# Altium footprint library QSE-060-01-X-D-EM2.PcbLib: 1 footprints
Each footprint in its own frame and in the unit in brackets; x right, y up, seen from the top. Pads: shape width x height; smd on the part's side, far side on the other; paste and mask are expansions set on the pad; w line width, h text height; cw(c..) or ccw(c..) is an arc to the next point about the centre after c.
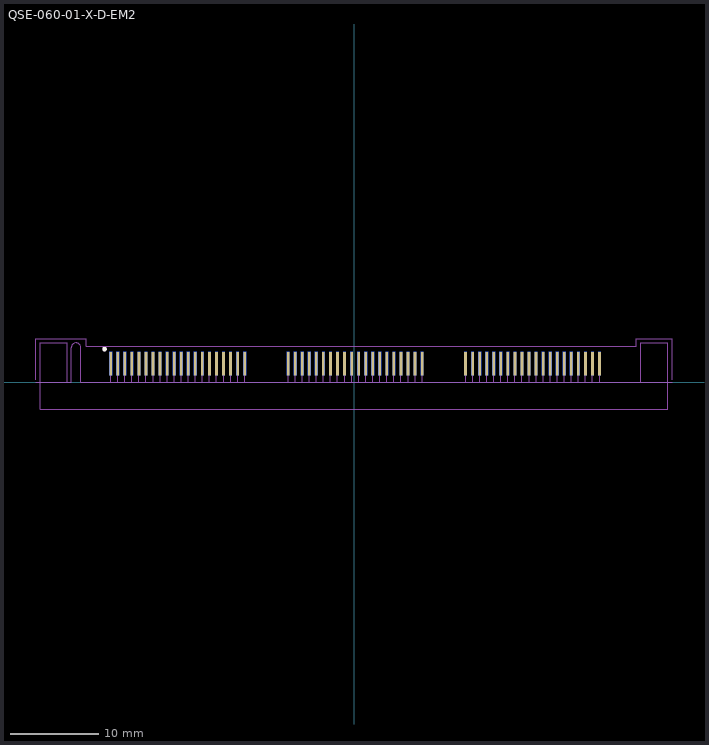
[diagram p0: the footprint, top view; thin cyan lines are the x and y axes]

## QSE-060-01-X-D-EM2 [mil] "0.80mm pitch, 120 pin, high speed socket strip"
height 142.91
pads (120):
  rect 12.01x105 smd far side mask+0: 1(-1086.71,82.5) 3(-1055.22,82.5) 5(-1023.72,82.5) 7(-992.22,82.5) 9(-960.73,82.5) 11(-929.23,82.5) 13(-897.74,82.5) 15(-866.24,82.5) 17(-834.74,82.5) 19(-803.25,82.5) 21(-771.75,82.5) 23(-740.26,82.5) 25(-708.76,82.5) 27(-677.26,82.5) 29(-645.77,82.5) 31(-614.27,82.5) 33(-582.78,82.5) 35(-551.28,82.5) 37(-519.78,82.5) 39(-488.29,82.5) 41(-294.19,82.5) 43(-262.7,82.5) 45(-231.2,82.5) 47(-199.7,82.5) 49(-168.21,82.5) 51(-136.71,82.5) 53(-105.22,82.5) 55(-73.72,82.5) 57(-42.22,82.5) 59(-10.73,82.5) 61(20.77,82.5) 63(52.26,82.5) 65(83.76,82.5) 67(115.26,82.5) 69(146.75,82.5) 71(178.25,82.5) 73(209.74,82.5) 75(241.24,82.5) 77(272.74,82.5) 79(304.23,82.5) 81(498.33,82.5) 83(529.82,82.5) 85(561.32,82.5) 87(592.82,82.5) 89(624.31,82.5) 91(655.81,82.5) 93(687.3,82.5) 95(718.8,82.5) 97(750.3,82.5) 99(781.79,82.5) 101(813.29,82.5) 103(844.78,82.5) 105(876.28,82.5) 107(907.78,82.5) 109(939.27,82.5) 111(970.77,82.5) 113(1002.26,82.5) 115(1033.76,82.5) 117(1065.26,82.5) 119(1096.75,82.5)
  rect 12.01x105 smd mask+0: 2(-1086.71,82.5) 4(-1055.22,82.5) 6(-1023.72,82.5) 8(-992.22,82.5) 10(-960.73,82.5) 12(-929.23,82.5) 14(-897.74,82.5) 16(-866.24,82.5) 18(-834.74,82.5) 20(-803.25,82.5) 22(-771.75,82.5) 24(-740.26,82.5) 26(-708.76,82.5) 28(-677.26,82.5) 30(-645.77,82.5) 32(-614.27,82.5) 34(-582.78,82.5) 36(-551.28,82.5) 38(-519.78,82.5) 40(-488.29,82.5) 42(-294.19,82.5) 44(-262.7,82.5) 46(-231.2,82.5) 48(-199.7,82.5) 50(-168.21,82.5) 52(-136.71,82.5) 54(-105.22,82.5) 56(-73.72,82.5) 58(-42.22,82.5) 60(-10.73,82.5) 62(20.77,82.5) 64(52.26,82.5) 66(83.76,82.5) 68(115.26,82.5) 70(146.75,82.5) 72(178.25,82.5) 74(209.74,82.5) 76(241.24,82.5) 78(272.74,82.5) 80(304.23,82.5) 82(498.33,82.5) 84(529.82,82.5) 86(561.32,82.5) 88(592.82,82.5) 90(624.31,82.5) 92(655.81,82.5) 94(687.3,82.5) 96(718.8,82.5) 98(750.3,82.5) 100(781.79,82.5) 102(813.29,82.5) 104(844.78,82.5) 106(876.28,82.5) 108(907.78,82.5) 110(939.27,82.5) 112(970.77,82.5) 114(1002.26,82.5) 116(1033.76,82.5) 118(1065.26,82.5) 120(1096.75,82.5)
Top Overlay:
  circle w9.84: c-1114.17,147.64 r4.92
Top Solder:
  lines w5: -1086.71,82.5 -1086.71,134.98 ; -1055.22,82.5 -1055.22,134.98 ; -1023.72,82.5 -1023.72,134.98 ; -992.22,82.5 -992.22,134.98 ; -960.73,82.5 -960.73,134.98 ; -929.23,82.5 -929.23,134.98 ; -897.74,82.5 -897.74,134.98 ; -866.24,82.5 -866.24,134.98 ; -834.74,82.5 -834.74,134.98 ; -803.25,82.5 -803.25,134.98 ; -771.75,82.5 -771.75,134.98 ; -740.26,82.5 -740.26,134.98 ; -708.76,82.5 -708.76,134.98 ; -677.26,82.5 -677.26,134.98 ; -645.77,82.5 -645.77,134.98 ; -614.27,82.5 -614.27,134.98 ; -582.78,82.5 -582.78,134.98 ; -551.28,82.5 -551.28,134.98 ; -519.78,82.5 -519.78,134.98 ; -488.29,82.5 -488.29,134.98 ; -294.19,82.5 -294.19,134.98 ; -262.7,82.5 -262.7,134.98 ; -231.2,82.5 -231.2,134.98 ; -199.7,82.5 -199.7,134.98 ; -168.21,82.5 -168.21,134.98 ; -136.71,82.5 -136.71,134.98 ; -105.22,82.5 -105.22,134.98 ; -73.72,82.5 -73.72,134.98 ; -42.22,82.5 -42.22,134.98 ; -10.73,82.5 -10.73,134.98 ; 20.77,82.5 20.77,134.98 ; 52.26,82.5 52.26,134.98 ; 83.76,82.5 83.76,134.98 ; 115.26,82.5 115.26,134.98 ; 146.75,82.5 146.75,134.98 ; 178.25,82.5 178.25,134.98 ; 209.74,82.5 209.74,134.98 ; 241.24,82.5 241.24,134.98 ; 272.74,82.5 272.74,134.98 ; 304.23,82.5 304.23,134.98 ; 498.33,82.5 498.33,134.98 ; 529.82,82.5 529.82,134.98 ; 561.32,82.5 561.32,134.98 ; 592.82,82.5 592.82,134.98 ; 624.31,82.5 624.31,134.98 ; 655.81,82.5 655.81,134.98 ; 687.3,82.5 687.3,134.98 ; 718.8,82.5 718.8,134.98 ; 750.3,82.5 750.3,134.98 ; 781.79,82.5 781.79,134.98 ; 813.29,82.5 813.29,134.98 ; 844.78,82.5 844.78,134.98 ; 876.28,82.5 876.28,134.98 ; 907.78,82.5 907.78,134.98 ; 939.27,82.5 939.27,134.98 ; 970.77,82.5 970.77,134.98 ; 1002.26,82.5 1002.26,134.98 ; 1033.76,82.5 1033.76,134.98 ; 1065.26,82.5 1065.26,134.98 ; 1096.75,82.5 1096.75,134.98
Bottom Solder:
  lines w5: -1086.71,82.5 -1086.71,134.98 ; -1055.22,82.5 -1055.22,134.98 ; -1023.72,82.5 -1023.72,134.98 ; -992.22,82.5 -992.22,134.98 ; -960.73,82.5 -960.73,134.98 ; -929.23,82.5 -929.23,134.98 ; -897.74,82.5 -897.74,134.98 ; -866.24,82.5 -866.24,134.98 ; -834.74,82.5 -834.74,134.98 ; -803.25,82.5 -803.25,134.98 ; -771.75,82.5 -771.75,134.98 ; -740.26,82.5 -740.26,134.98 ; -708.76,82.5 -708.76,134.98 ; -677.26,82.5 -677.26,134.98 ; -645.77,82.5 -645.77,134.98 ; -614.27,82.5 -614.27,134.98 ; -582.78,82.5 -582.78,134.98 ; -551.28,82.5 -551.28,134.98 ; -519.78,82.5 -519.78,134.98 ; -488.29,82.5 -488.29,134.98 ; -294.19,82.5 -294.19,134.98 ; -262.7,82.5 -262.7,134.98 ; -231.2,82.5 -231.2,134.98 ; -199.7,82.5 -199.7,134.98 ; -168.21,82.5 -168.21,134.98 ; -136.71,82.5 -136.71,134.98 ; -105.22,82.5 -105.22,134.98 ; -73.72,82.5 -73.72,134.98 ; -42.22,82.5 -42.22,134.98 ; -10.73,82.5 -10.73,134.98 ; 20.77,82.5 20.77,134.98 ; 52.26,82.5 52.26,134.98 ; 83.76,82.5 83.76,134.98 ; 115.26,82.5 115.26,134.98 ; 146.75,82.5 146.75,134.98 ; 178.25,82.5 178.25,134.98 ; 209.74,82.5 209.74,134.98 ; 241.24,82.5 241.24,134.98 ; 272.74,82.5 272.74,134.98 ; 304.23,82.5 304.23,134.98 ; 498.33,82.5 498.33,134.98 ; 529.82,82.5 529.82,134.98 ; 561.32,82.5 561.32,134.98 ; 592.82,82.5 592.82,134.98 ; 624.31,82.5 624.31,134.98 ; 655.81,82.5 655.81,134.98 ; 687.3,82.5 687.3,134.98 ; 718.8,82.5 718.8,134.98 ; 750.3,82.5 750.3,134.98 ; 781.79,82.5 781.79,134.98 ; 813.29,82.5 813.29,134.98 ; 844.78,82.5 844.78,134.98 ; 876.28,82.5 876.28,134.98 ; 907.78,82.5 907.78,134.98 ; 939.27,82.5 939.27,134.98 ; 970.77,82.5 970.77,134.98 ; 1002.26,82.5 1002.26,134.98 ; 1033.76,82.5 1033.76,134.98 ; 1065.26,82.5 1065.26,134.98 ; 1096.75,82.5 1096.75,134.98
Mechanical 12:
  lines w0.04: -1421.26,0 -1262.7,0 -1262.7,153.5 ; -1219.7,153.5 -1219.7,0 1421.26,0
Mechanical 13:
  circle w9.84: c-1114.17,147.64 r4.92
  lines w3.94: -1086.71,0 -1086.71,82.5 ; -1055.22,0 -1055.22,82.5 ; -1023.72,0 -1023.72,82.5 ; -992.22,0 -992.22,82.5 ; -960.73,0 -960.73,82.5 ; -929.23,0 -929.23,82.5 ; -897.74,0 -897.74,82.5 ; -866.24,0 -866.24,82.5 ; -834.74,0 -834.74,82.5 ; -803.25,0 -803.25,82.5 ; -771.75,0 -771.75,82.5 ; -740.26,0 -740.26,82.5 ; -708.76,0 -708.76,82.5 ; -677.26,0 -677.26,82.5 ; -645.77,0 -645.77,82.5 ; -614.27,0 -614.27,82.5 ; -582.78,0 -582.78,82.5 ; -551.28,0 -551.28,82.5 ; -519.78,0 -519.78,82.5 ; -488.29,0 -488.29,82.5 ; -294.19,0 -294.19,82.5 ; -262.7,0 -262.7,82.5 ; -231.2,0 -231.2,82.5 ; -199.7,0 -199.7,82.5 ; -168.21,0 -168.21,82.5 ; -136.71,0 -136.71,82.5 ; -105.22,0 -105.22,82.5 ; -73.72,0 -73.72,82.5 ; -42.22,0 -42.22,82.5 ; -10.73,0 -10.73,82.5 ; 20.77,0 20.77,82.5 ; 52.26,0 52.26,82.5 ; 83.76,0 83.76,82.5 ; 115.26,0 115.26,82.5 ; 146.75,0 146.75,82.5 ; 178.25,0 178.25,82.5 ; 209.74,0 209.74,82.5 ; 241.24,0 241.24,82.5 ; 272.74,0 272.74,82.5 ; 304.23,0 304.23,82.5 ; 498.33,0 498.33,82.5 ; 529.82,0 529.82,82.5 ; 561.32,0 561.32,82.5 ; 592.82,0 592.82,82.5 ; 624.31,0 624.31,82.5 ; 655.81,0 655.81,82.5 ; 687.3,0 687.3,82.5 ; 718.8,0 718.8,82.5 ; 750.3,0 750.3,82.5 ; 781.79,0 781.79,82.5 ; 813.29,0 813.29,82.5 ; 844.78,0 844.78,82.5 ; 876.28,0 876.28,82.5 ; 907.78,0 907.78,82.5 ; 939.27,0 939.27,82.5 ; 970.77,0 970.77,82.5 ; 1002.26,0 1002.26,82.5 ; 1033.76,0 1033.76,82.5 ; 1065.26,0 1065.26,82.5 ; 1096.75,0 1096.75,82.5 ; -1401.34,-120.08 1401.38,-120.08 1401.38,175 1281.36,175 1281.36,0 -1219.7,0 -1219.7,153.5 ccw(c-1241.2,153.5) -1262.7,153.5 -1262.7,0 -1281.34,0 -1281.34,175 -1401.34,175 -1401.34,-120.08
  text ".Designator" at 0,0 h60
Mechanical 15:
  lines w1.97: -1421.26,9.84 -1421.26,192.91 -1196.85,192.91 -1196.85,159.45 1259.84,159.45 1259.84,192.91 1421.26,192.91 1421.26,9.84
Drill Drawing:
  lines w0.04: -1262.7,153.5 cw(c-1241.2,153.5) -1219.7,153.5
